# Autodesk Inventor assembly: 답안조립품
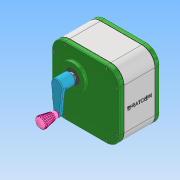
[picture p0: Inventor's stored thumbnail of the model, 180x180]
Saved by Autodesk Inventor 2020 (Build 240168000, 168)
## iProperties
Created: 2022-03
Part Number: 답안조립품
Document SubType Name: Assembly
Designer: Administrator
Author: Administrator
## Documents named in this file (14)
- C:\Users\Administrator\Documents\Inventor\620306V1021\답안조립품.iam
- C:\Users\Administrator\Documents\Inventor\620306V1021\620306V1021\개스킷.ipt
- C:\Users\Administrator\Documents\Inventor\620306V1021\620306V1021\뒤커버.ipt
- C:\Users\Administrator\Documents\Inventor\620306V1021\620306V1021\메인축.ipt
- C:\Users\Administrator\Documents\Inventor\620306V1021\620306V1021\베어링 608.ipt
- C:\Users\Administrator\Documents\Inventor\620306V1021\620306V1021\베어링 6003.ipt
- C:\Users\Administrator\Documents\Inventor\620306V1021\620306V1021\본체.ipt
- C:\Users\Administrator\Documents\Inventor\620306V1021\620306V1021\볼트 M4.ipt
- C:\Users\Administrator\Documents\Inventor\620306V1021\620306V1021\서브축.ipt
- C:\Users\Administrator\Documents\Inventor\620306V1021\620306V1021\손잡이A.ipt
- C:\Users\Administrator\Documents\Inventor\620306V1021\620306V1021\손잡이B.ipt
- C:\Users\Administrator\Documents\Inventor\620306V1021\620306V1021\앞커버.ipt
- C:\Users\Administrator\Documents\Inventor\620306V1021\620306V1021\오일실 8 x 22 x 7.ipt
- C:\Users\Administrator\Documents\Inventor\620306V1021\620306V1021\오일실 17 x 32 x 8.ipt
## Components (2 placed, 1 different names)
1. 개스킷:1
2. 개스킷:2
## Component patterns: 구성요소 패턴 1:2 (2 elements), 구성요소 패턴 3:2 (2 elements)
